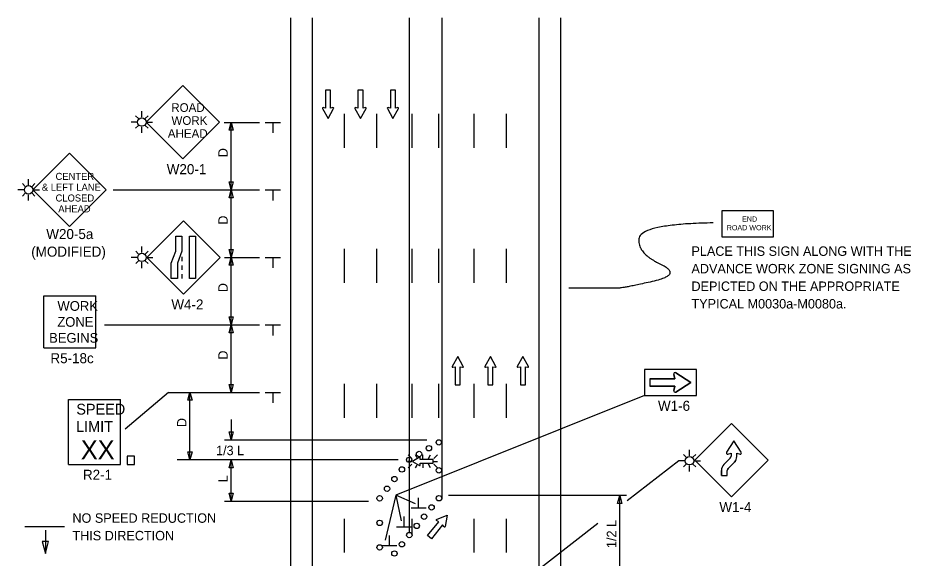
# Model space of a CAD drawing. Extents: x 16038 to 19504, y 5710 to 8321.
# Drawn here: x 16736 to 17399, y 6525 to 6925 of the extents above; entities that cross this region are included whole.
import ezdxf

# ---------------------------------------------------------------- set-up
doc = ezdxf.new("R2010")
doc.units = 0
for name, color, linetype in [('ALI_LEGAL_EX', 7, 'Continuous'), ('Level 3', 7, 'Continuous'), ('MT_SCRATCH_LEVEL_E', 7, 'Continuous'), ('PAVT_EDGE_EX', 7, 'Continuous'), ('TRAFFIC_SIGNS_PR', 7, 'Continuous'), ('TYPICAL_EX', 7, 'Continuous'), ('TYPICAL_TEXT_DIMEN_PR', 7, 'Continuous')]:
    doc.layers.add(name, color=color, linetype=linetype)

msp = doc.modelspace()

# ---------------------------------------------------------------- linework, layer by layer
at = {"layer": 'ALI_LEGAL_EX'}
for points in [[(16978.71, 6829.12), (16978.71, 6854.12)], [(17002.71, 6829.12), (17002.71, 6854.12)], [(17028.71, 6829.12), (17028.71, 6854.12)], [(17048.71, 6829.12), (17048.71, 6854.12)], [(17074.71, 6829.12), (17074.71, 6854.12)], [(17098.71, 6829.12), (17098.71, 6854.12)], [(16978.71, 6729.12), (16978.71, 6754.12)], [(17002.71, 6729.12), (17002.71, 6754.12)], [(17028.71, 6729.12), (17028.71, 6754.12)], [(17048.71, 6729.12), (17048.71, 6754.12)], [(17074.71, 6729.12), (17074.71, 6754.12)], [(17098.71, 6729.12), (17098.71, 6754.12)], [(16978.71, 6629.12), (16978.71, 6654.12)], [(17002.71, 6629.12), (17002.71, 6654.12)], [(17028.71, 6629.12), (17028.71, 6654.12)], [(17048.71, 6629.12), (17048.71, 6654.12)], [(17074.71, 6629.12), (17074.71, 6654.12)], [(17098.71, 6629.12), (17098.71, 6654.12)], [(16978.71, 6529.12), (16978.71, 6554.12)], [(17028.71, 6542.73), (17028.71, 6554.12)], [(17074.71, 6529.12), (17074.71, 6554.12)], [(17098.71, 6529.12), (17098.71, 6554.12)]]:
    msp.add_lwpolyline(points, dxfattribs=at)
at = {"layer": 'Level 3'}
msp.add_line((16848.03, 6647.88), (16815.91, 6620.5), dxfattribs=at)
at = {"layer": 'MT_SCRATCH_LEVEL_E'}
for p, q in [((16968.31, 6871.76), (16964.57, 6871.76)), ((16964.57, 6871.76), (16964.57, 6858.5)), ((16968.31, 6871.76), (16964.57, 6871.76)), ((16964.57, 6871.76), (16964.57, 6858.5)), ((16968.31, 6858.5), (16968.31, 6871.76)), ((16968.31, 6858.5), (16968.31, 6871.76)), ((16992.38, 6871.76), (16988.64, 6871.76)), ((16988.64, 6871.76), (16988.64, 6858.5)), ((16992.38, 6871.76), (16988.64, 6871.76)), ((16988.64, 6871.76), (16988.64, 6858.5)), ((16992.38, 6858.5), (16992.38, 6871.76)), ((16992.38, 6858.5), (16992.38, 6871.76)), ((17016.45, 6871.76), (17012.71, 6871.76)), ((17012.71, 6871.76), (17012.71, 6858.5)), ((17016.45, 6871.76), (17012.71, 6871.76)), ((17012.71, 6871.76), (17012.71, 6858.5)), ((17016.45, 6858.5), (17016.45, 6871.76)), ((17016.45, 6858.5), (17016.45, 6871.76)), ((16962.31, 6858.13), (16966.46, 6850.89)), ((16962.31, 6858.13), (16966.46, 6850.89)), ((16964.57, 6858.5), (16962.79, 6858.82)), ((16964.57, 6858.5), (16962.79, 6858.82)), ((16966.46, 6850.89), (16970.57, 6858.13)), ((16966.46, 6850.89), (16970.57, 6858.13)), ((16970.08, 6858.82), (16968.31, 6858.5)), ((16970.08, 6858.82), (16968.31, 6858.5)), ((16986.38, 6858.13), (16990.53, 6850.89)), ((16986.38, 6858.13), (16990.53, 6850.89)), ((16988.64, 6858.5), (16986.86, 6858.82)), ((16988.64, 6858.5), (16986.86, 6858.82)), ((16990.53, 6850.89), (16994.64, 6858.13)), ((16990.53, 6850.89), (16994.64, 6858.13)), ((16994.16, 6858.82), (16992.38, 6858.5)), ((16994.16, 6858.82), (16992.38, 6858.5)), ((17010.45, 6858.13), (17014.6, 6850.89)), ((17010.45, 6858.13), (17014.6, 6850.89)), ((17012.71, 6858.5), (17010.93, 6858.82)), ((17012.71, 6858.5), (17010.93, 6858.82)), ((17014.6, 6850.89), (17018.71, 6858.13)), ((17014.6, 6850.89), (17018.71, 6858.13)), ((17018.23, 6858.82), (17016.45, 6858.5)), ((17018.23, 6858.82), (17016.45, 6858.5)), ((17062.58, 6674.37), (17058.47, 6667.13)), ((17062.58, 6674.37), (17058.47, 6667.13)), ((17066.73, 6667.13), (17062.58, 6674.37)), ((17066.73, 6667.13), (17062.58, 6674.37)), ((17086.85, 6674.37), (17082.74, 6667.13)), ((17086.85, 6674.37), (17082.74, 6667.13)), ((17090.99, 6667.13), (17086.85, 6674.37)), ((17090.99, 6667.13), (17086.85, 6674.37)), ((17110.92, 6674.37), (17106.81, 6667.13)), ((17110.92, 6674.37), (17106.81, 6667.13)), ((17115.07, 6667.13), (17110.92, 6674.37)), ((17115.07, 6667.13), (17110.92, 6674.37)), ((17058.95, 6666.44), (17060.73, 6666.76)), ((17058.95, 6666.44), (17060.73, 6666.76)), ((17060.73, 6666.76), (17060.73, 6653.5)), ((17060.73, 6666.76), (17060.73, 6653.5)), ((17064.47, 6653.5), (17064.47, 6666.76)), ((17064.47, 6666.76), (17066.25, 6666.44)), ((17064.47, 6653.5), (17064.47, 6666.76)), ((17064.47, 6666.76), (17066.25, 6666.44)), ((17083.22, 6666.44), (17085, 6666.76)), ((17083.22, 6666.44), (17085, 6666.76)), ((17085, 6666.76), (17085, 6653.5)), ((17085, 6666.76), (17085, 6653.5)), ((17088.74, 6653.5), (17088.74, 6666.76)), ((17088.74, 6666.76), (17090.52, 6666.44)), ((17088.74, 6653.5), (17088.74, 6666.76)), ((17088.74, 6666.76), (17090.52, 6666.44)), ((17107.29, 6666.44), (17109.07, 6666.76)), ((17107.29, 6666.44), (17109.07, 6666.76)), ((17109.07, 6666.76), (17109.07, 6653.5)), ((17109.07, 6666.76), (17109.07, 6653.5)), ((17112.81, 6653.5), (17112.81, 6666.76)), ((17112.81, 6666.76), (17114.59, 6666.44)), ((17112.81, 6653.5), (17112.81, 6666.76)), ((17112.81, 6666.76), (17114.59, 6666.44)), ((17060.73, 6653.5), (17064.47, 6653.5)), ((17060.73, 6653.5), (17064.47, 6653.5)), ((17085, 6653.5), (17088.74, 6653.5)), ((17085, 6653.5), (17088.74, 6653.5)), ((17109.07, 6653.5), (17112.81, 6653.5)), ((17109.07, 6653.5), (17112.81, 6653.5)), ((17040.17, 6541.74), (17048.49, 6552.06)), ((17040.17, 6541.74), (17048.49, 6552.06)), ((17048.49, 6552.06), (17046.91, 6552.93)), ((17048.49, 6552.06), (17046.91, 6552.93)), ((17046.96, 6553.77), (17054.73, 6556.81)), ((17046.96, 6553.77), (17054.73, 6556.81)), ((17054.73, 6556.81), (17053.39, 6548.59)), ((17054.73, 6556.81), (17053.39, 6548.59)), ((17051.4, 6549.72), (17043.09, 6539.39)), ((17051.4, 6549.72), (17043.09, 6539.39)), ((17052.59, 6548.36), (17051.4, 6549.72)), ((17052.59, 6548.36), (17051.4, 6549.72)), ((17043.09, 6539.39), (17040.17, 6541.74)), ((17043.09, 6539.39), (17040.17, 6541.74))]:
    msp.add_line(p, q, dxfattribs=at)
for centre, start, end in [((16962.72, 6858.36), 80.03619, 209.77312), ((16962.72, 6858.36), 80.03619, 209.77312), ((16970.16, 6858.36), 330.42484, 99.96381), ((16970.16, 6858.36), 330.42484, 99.96381), ((16986.79, 6858.36), 80.03619, 209.77312), ((16986.79, 6858.36), 80.03619, 209.77312), ((16994.23, 6858.36), 330.42484, 99.96381), ((16994.23, 6858.36), 330.42484, 99.96381), ((17010.86, 6858.36), 80.03619, 209.77312), ((17010.86, 6858.36), 80.03619, 209.77312), ((17018.3, 6858.36), 330.42484, 99.96381), ((17018.3, 6858.36), 330.42484, 99.96381), ((17058.88, 6666.9), 150.42484, 279.96381), ((17058.88, 6666.9), 150.42484, 279.96381), ((17066.32, 6666.9), 260.03619, 29.77312), ((17066.32, 6666.9), 260.03619, 29.77312), ((17083.14, 6666.9), 150.42484, 279.96381), ((17083.14, 6666.9), 150.42484, 279.96381), ((17090.59, 6666.9), 260.03619, 29.77312), ((17090.59, 6666.9), 260.03619, 29.77312), ((17107.22, 6666.9), 150.42484, 279.96381), ((17107.22, 6666.9), 150.42484, 279.96381), ((17114.66, 6666.9), 260.03619, 29.77312), ((17114.66, 6666.9), 260.03619, 29.77312), ((17047.14, 6553.34), 111.38609, 241.12301), ((17047.14, 6553.34), 111.38609, 241.12301), ((17052.94, 6548.67), 221.1954, 350.73437), ((17052.94, 6548.67), 221.1954, 350.73437)]:
    msp.add_arc(centre, 0.463, start, end, dxfattribs=at)
at = {"layer": 'PAVT_EDGE_EX'}
for p, q in [((16954.71, 6925.32), (16954.71, 6077.44)), ((17026.71, 6925.32), (17026.71, 6544.7)), ((17050.71, 6925.32), (17050.71, 6570.98)), ((17122.71, 6925.32), (17122.71, 6077.44)), ((17138.71, 6925.32), (17138.71, 6077.44)), ((17026.71, 6816.67), (17026.71, 6543.65)), ((17050.71, 6816.67), (17050.71, 6568.76)), ((16938.71, 6780.67), (16938.71, 6077.44))]:
    msp.add_line(p, q, dxfattribs=at)
at = {"layer": 'TRAFFIC_SIGNS_PR'}
for p, q in [((16858.67, 6875.33), (16831.49, 6848.14)), ((16885.86, 6848.14), (16858.67, 6875.33)), ((16825.82, 6850.66), (16823.71, 6852.77)), ((16828.33, 6851.7), (16828.33, 6856.2)), ((16830.85, 6850.66), (16832.95, 6852.77)), ((16825.18, 6848.14), (16820.34, 6848.14)), ((16825.82, 6845.63), (16823.71, 6843.52)), ((16828.33, 6840.18), (16828.33, 6844.59)), ((16830.85, 6845.63), (16832.95, 6843.52)), ((16831.49, 6848.14), (16836.37, 6848.14)), ((16831.49, 6848.14), (16858.67, 6820.96)), ((16858.67, 6820.96), (16885.86, 6848.14)), ((16774.75, 6825.07), (16747.57, 6797.88)), ((16801.94, 6797.88), (16774.75, 6825.07)), ((16744.41, 6801.44), (16744.41, 6805.94)), ((16741.26, 6797.88), (16736.42, 6797.88)), ((16741.9, 6800.4), (16739.79, 6802.5)), ((16746.93, 6800.4), (16749.03, 6802.5)), ((16747.57, 6797.88), (16752.45, 6797.88)), ((16747.57, 6797.88), (16774.75, 6770.69)), ((16774.75, 6770.69), (16801.94, 6797.88)), ((16741.9, 6795.37), (16739.79, 6793.26)), ((16744.41, 6789.92), (16744.41, 6794.33)), ((16746.93, 6795.37), (16749.03, 6793.26)), ((16859.31, 6775.01), (16832.16, 6747.86)), ((16886.46, 6747.86), (16859.31, 6775.01)), ((16825.91, 6750.37), (16823.8, 6752.48)), ((16828.42, 6751.41), (16828.42, 6755.91)), ((16830.94, 6750.37), (16833.04, 6752.48)), ((16825.27, 6747.86), (16820.43, 6747.86)), ((16825.91, 6745.35), (16823.8, 6743.24)), ((16828.42, 6739.89), (16828.42, 6744.3)), ((16830.94, 6745.35), (16833.04, 6743.24)), ((16831.58, 6747.86), (16836.46, 6747.86)), ((16832.16, 6747.86), (16859.31, 6720.71)), ((16858.06, 6748.35), (16858.06, 6745.15)), ((16859.31, 6720.71), (16886.46, 6747.86)), ((16858.06, 6741.95), (16858.06, 6738.75)), ((16858.06, 6735.55), (16858.06, 6732.35)), ((16755.78, 6680.91), (16755.78, 6719.31)), ((16755.78, 6719.31), (16794.18, 6719.31)), ((16794.18, 6680.91), (16794.18, 6719.31)), ((16755.78, 6680.91), (16794.18, 6680.91)), ((17205.2, 6658.02), (17223.6, 6658.02)), ((17205.2, 6658.02), (17205.2, 6652.42)), ((17223.6, 6658.02), (17222.76, 6661.08)), ((17224.44, 6662.32), (17235.6, 6655.22)), ((17223.6, 6652.42), (17205.2, 6652.42)), ((17222.76, 6649.36), (17223.6, 6652.42)), ((17235.6, 6655.22), (17224.44, 6648.12)), ((16774.02, 6642.54), (16812.42, 6642.54)), ((16774.02, 6594.54), (16774.02, 6642.54)), ((16812.42, 6594.54), (16812.42, 6642.54)), ((17265.66, 6624.87), (17238.51, 6597.72)), ((17292.81, 6597.72), (17265.66, 6624.87)), ((17234.55, 6600.8), (17234.55, 6605.3)), ((17025.79, 6601.61), (17028.61, 6598.79)), ((17032.51, 6599.43), (17031.25, 6601.61)), ((17036.7, 6598.79), (17036.7, 6601.61)), ((17040.83, 6598.79), (17042.46, 6601.61)), ((17044.78, 6598.79), (17047.6, 6601.61)), ((17232.04, 6599.76), (17229.93, 6601.86)), ((17237.06, 6599.76), (17239.17, 6601.86)), ((17260, 6594.46), (17264.72, 6599.18)), ((17264.72, 6599.18), (17260, 6594.46)), ((16774.02, 6594.54), (16812.42, 6594.54)), ((17028.61, 6596.76), (17025.79, 6596.76)), ((17025.79, 6591.91), (17028.61, 6594.73)), ((17031.23, 6591.91), (17032.44, 6594)), ((17036.7, 6594.73), (17036.7, 6591.91)), ((17042.49, 6591.91), (17040.86, 6594.73)), ((17044.78, 6596.76), (17047.6, 6596.76)), ((17044.78, 6594.73), (17047.6, 6591.91)), ((17231.4, 6597.24), (17226.56, 6597.24)), ((17232.04, 6594.73), (17229.93, 6592.62)), ((17234.55, 6589.28), (17234.55, 6593.69)), ((17237.06, 6594.73), (17239.17, 6592.62)), ((17237.7, 6597.24), (17242.58, 6597.24)), ((17238.51, 6597.72), (17265.66, 6570.56)), ((17263.05, 6591.41), (17267.77, 6596.13)), ((17263.06, 6591.41), (17267.77, 6596.13)), ((17265.66, 6570.56), (17292.81, 6597.72)), ((17258.14, 6586.34), (17258.14, 6590.04)), ((17258.14, 6586.34), (17262.45, 6586.34)), ((17262.45, 6586.34), (17262.45, 6590.04))]:
    msp.add_line(p, q, dxfattribs=at)
for points in [[(17258.49, 6763.22), (17296.89, 6763.22), (17296.89, 6782.42), (17258.49, 6782.42)], [(16858.06, 6763.6), (16858.06, 6752.41), (16854.72, 6743.53), (16854.72, 6732.35), (16850.23, 6732.35), (16850.23, 6743.53), (16853.57, 6752.41), (16853.57, 6763.6)], [(16868.2, 6763.6), (16868.2, 6732.35), (16863.71, 6732.35), (16863.71, 6763.6)], [(17201.2, 6645.62), (17239.6, 6645.62), (17239.6, 6664.82), (17201.2, 6664.82)], [(16817.43, 6594.54), (16823.03, 6594.54), (16823.03, 6600.71), (16817.43, 6600.71)]]:
    msp.add_lwpolyline(points, close=True, dxfattribs=at)
for points in [[(17222.76, 6661.08), (17223.6, 6658.02), (17205.2, 6658.02), (17205.2, 6652.42), (17223.6, 6652.42), (17222.76, 6649.36)], [(17224.44, 6648.12), (17235.6, 6655.22), (17224.44, 6662.32)], [(17272.92, 6603.45), (17267.44, 6612.06), (17261.96, 6603.45)], [(17272.92, 6603.45), (17267.44, 6612.06), (17261.96, 6603.45)], [(17034.37, 6599.78), (17029.06, 6596.76), (17034.37, 6593.72)], [(17034.87, 6594.08), (17034.64, 6595.37), (17044.36, 6595.37), (17044.36, 6598.12), (17034.64, 6598.12), (17034.87, 6599.42)], [(17262.92, 6602.15), (17265.28, 6602.8), (17265.28, 6600.51)], [(17262.92, 6602.15), (17263.75, 6602.38), (17265.28, 6602.8), (17265.28, 6600.51)], [(17269.59, 6600.44), (17269.6, 6602.8), (17271.96, 6602.15)], [(17258.14, 6590.04), (17258.14, 6586.34), (17262.45, 6586.34), (17262.45, 6590.04)]]:
    msp.add_lwpolyline(points, dxfattribs=at)
for centre, radius in [((16828.33, 6848.14), 3.15), ((16744.41, 6797.88), 3.15), ((16828.42, 6747.86), 3.15), ((17048.6, 6610.8), 2), ((17048.6, 6610.8), 2), ((17041.27, 6606.49), 2), ((17026.61, 6597.88), 2), ((17033.94, 6602.19), 2), ((17234.55, 6597.24), 3.15), ((17021.19, 6590.75), 2), ((17048.65, 6590.13), 2), ((17015.7, 6583.62), 2), ((17010.2, 6576.49), 2), ((17048.71, 6569.46), 2), ((17004.71, 6569.36), 2), ((17004.71, 6569.36), 2), ((17004.71, 6569.36), 2), ((17004.71, 6569.36), 2), ((17004.71, 6569.36), 2), ((17043.21, 6562.63), 2), ((17004.71, 6551.18), 2), ((17037.71, 6555.8), 2), ((17032.21, 6548.97), 2), ((17026.71, 6542.14), 2), ((17004.71, 6533), 2), ((17021.21, 6535.31), 2), ((17015.71, 6528.48), 2)]:
    msp.add_circle(centre, radius, dxfattribs=at)
for centre, radius, start, end in [((17223.84, 6661.38), 1.12, 57.53038, 195.32692), ((17223.84, 6661.38), 1.12, 57.53038, 195.32692), ((17223.84, 6649.06), 1.12, 164.67308, 302.46962), ((17223.84, 6649.06), 1.12, 164.67308, 302.46963), ((17034.53, 6599.48), 0.341, 350.73078, 118.89165), ((17262.69, 6602.99), 0.864, 147.52044, 285.3986), ((17262.69, 6602.99), 0.866, 147.52881, 285.38519), ((17263.43, 6600.5), 1.85, 314.2123, 0.1238), ((17263.43, 6600.5), 1.85, 314.21254, 0), ((17263.43, 6600.5), 6.17, 314.21254, 359.38189), ((17263.43, 6600.5), 6.17, 314.76872, 359.37555), ((17272.19, 6602.99), 0.866, 254.67989, 32.28036), ((17034.53, 6594.02), 0.341, 241.48329, 9.95933), ((17264.3, 6590.04), 6.17, 134.21254, 180), ((17264.3, 6590.04), 6.17, 134.21254, 180), ((17264.3, 6590.04), 6.17, 134.21172, 180), ((17264.3, 6590.04), 1.85, 132.37199, 180), ((17264.3, 6590.04), 1.85, 134.21254, 180)]:
    msp.add_arc(centre, radius, start, end, dxfattribs=at)
at = {"layer": 'TYPICAL_EX'}
msp.add_line((16938.71, 6925.32), (16938.71, 6077.44), dxfattribs=at)
at = {"layer": 'TYPICAL_TEXT_DIMEN_PR'}
for p, q in [((16889.35, 6847.88), (16915.61, 6847.88)), ((16889.61, 6847.88), (16915.61, 6847.88)), ((16893.04, 6842.02), (16894.61, 6847.88)), ((16894.61, 6797.88), (16894.61, 6847.88)), ((16894.61, 6847.88), (16896.18, 6842.02)), ((16919.86, 6847.88), (16931.11, 6847.88)), ((16925.49, 6847.88), (16925.49, 6840.1)), ((16894.61, 6842.02), (16893.04, 6842.02)), ((16896.18, 6842.02), (16894.61, 6842.02)), ((16894.61, 6797.88), (16893.04, 6803.74)), ((16893.04, 6803.74), (16894.61, 6803.74)), ((16894.61, 6803.74), (16896.18, 6803.74)), ((16896.18, 6803.74), (16894.61, 6797.88)), ((16807.15, 6797.88), (16915.61, 6797.88)), ((16889.61, 6797.88), (16915.61, 6797.88)), ((16893.04, 6792.02), (16894.61, 6797.88)), ((16894.61, 6797.88), (16896.18, 6792.02)), ((16894.61, 6747.88), (16894.61, 6797.88)), ((16919.86, 6797.88), (16931.11, 6797.88)), ((16925.49, 6797.88), (16925.49, 6790.1)), ((16894.61, 6792.02), (16893.04, 6792.02)), ((16896.18, 6792.02), (16894.61, 6792.02)), ((16894.61, 6747.88), (16893.04, 6753.74)), ((16893.04, 6753.74), (16894.61, 6753.74)), ((16894.61, 6753.74), (16896.18, 6753.74)), ((16896.18, 6753.74), (16894.61, 6747.88)), ((16889.61, 6747.88), (16915.61, 6747.88)), ((16893.04, 6742.02), (16894.61, 6747.88)), ((16894.61, 6747.88), (16896.18, 6742.02)), ((16894.61, 6697.88), (16894.61, 6747.88)), ((16919.86, 6747.88), (16931.11, 6747.88)), ((16925.49, 6747.88), (16925.49, 6740.1)), ((16894.61, 6742.02), (16893.04, 6742.02)), ((16896.18, 6742.02), (16894.61, 6742.02)), ((16800.57, 6697.88), (16915.61, 6697.88)), ((16894.61, 6697.88), (16893.04, 6703.74)), ((16893.04, 6703.74), (16894.61, 6703.74)), ((16893.04, 6692.02), (16894.61, 6697.88)), ((16894.61, 6703.74), (16896.18, 6703.74)), ((16896.18, 6703.74), (16894.61, 6697.88)), ((16894.61, 6647.88), (16894.61, 6697.88)), ((16894.61, 6697.88), (16896.18, 6692.02)), ((16919.86, 6697.88), (16931.11, 6697.88)), ((16925.49, 6697.88), (16925.49, 6690.1)), ((16894.61, 6692.02), (16893.04, 6692.02)), ((16896.18, 6692.02), (16894.61, 6692.02)), ((16894.61, 6647.88), (16893.04, 6653.74)), ((16893.04, 6653.74), (16894.61, 6653.74)), ((16894.61, 6653.74), (16896.18, 6653.74)), ((16896.18, 6653.74), (16894.61, 6647.88)), ((16848.03, 6647.88), (16915.61, 6647.88)), ((16862.46, 6642.02), (16864.03, 6647.88)), ((16864.03, 6647.88), (16865.6, 6642.02)), ((16864.03, 6597.88), (16864.03, 6647.88)), ((16919.86, 6647.88), (16931.11, 6647.88)), ((16925.49, 6647.88), (16925.49, 6640.1)), ((17201.2, 6645.62), (17016.78, 6571.82)), ((16864.03, 6642.02), (16862.46, 6642.02)), ((16865.6, 6642.02), (16864.03, 6642.02)), ((16894.61, 6627.73), (16894.61, 6612.8)), ((16894.61, 6612.8), (16893.04, 6618.67)), ((16893.04, 6618.67), (16894.61, 6618.67)), ((16894.61, 6618.67), (16896.18, 6618.67)), ((16896.18, 6618.67), (16894.61, 6612.8)), ((16889.61, 6612.8), (17039.81, 6612.8)), ((17018.36, 6597.88), (16854.51, 6597.88)), ((16864.03, 6597.88), (16862.46, 6603.74)), ((16862.46, 6603.74), (16864.03, 6603.74)), ((16864.03, 6603.74), (16865.6, 6603.74)), ((16865.6, 6603.74), (16864.03, 6597.88)), ((16893.04, 6592.02), (16894.61, 6597.88)), ((16894.61, 6567.35), (16894.61, 6597.88)), ((16894.61, 6597.88), (16896.18, 6592.02)), ((16894.61, 6592.02), (16893.04, 6592.02)), ((16896.18, 6592.02), (16894.61, 6592.02)), ((17226.56, 6597.24), (17188.25, 6567.51)), ((16894.61, 6567.35), (16893.04, 6573.21)), ((16893.04, 6573.21), (16894.61, 6573.21)), ((16894.61, 6573.21), (16896.18, 6573.21)), ((16896.18, 6573.21), (16894.61, 6567.35)), ((17016.78, 6571.82), (17008.81, 6538.48)), ((17031.18, 6565.37), (17016.78, 6571.82)), ((17016.78, 6571.82), (17020.55, 6552.7)), ((17187.71, 6571.46), (17055.85, 6571.46)), ((17181.14, 6565.6), (17182.71, 6571.46)), ((17182.71, 6514.82), (17182.71, 6571.46)), ((17182.71, 6571.46), (17184.28, 6565.6)), ((16889.61, 6567.35), (16996.54, 6567.35)), ((17033.62, 6562), (17033.62, 6569.78)), ((17182.71, 6565.6), (17181.14, 6565.6)), ((17184.28, 6565.6), (17182.71, 6565.6)), ((17039.24, 6562), (17027.99, 6562)), ((17022.79, 6548.07), (17022.79, 6555.86)), ((16771.04, 6548.22), (16741.6, 6548.22)), ((16756.86, 6545.72), (16756.86, 6528.6)), ((17028.41, 6548.07), (17017.16, 6548.07)), ((17166.55, 6550.67), (17039.04, 6451.72)), ((17011.96, 6534.15), (17011.96, 6541.93)), ((16756.86, 6537.39), (16754.5, 6537.39)), ((16754.5, 6537.39), (16756.86, 6528.6)), ((16756.86, 6528.6), (16759.22, 6537.39)), ((16759.22, 6537.39), (16756.86, 6537.39)), ((17017.58, 6534.15), (17006.33, 6534.15))]:
    msp.add_line(p, q, dxfattribs=at)
msp.add_open_spline([(17252.01, 6773.46), (17198.35, 6772.49), (17195.66, 6751.1), (17229.65, 6735.08), (17185.37, 6725.18), (17180.01, 6725.18), (17144.94, 6725.18)], degree=2, dxfattribs=at)

# ---------------------------------------------------------------- texts
at = {"layer": 'TRAFFIC_SIGNS_PR'}
for s, height, p in [('ROAD', 6.408, (16850.2, 6855.69)), ('WORK', 6.408, (16850.31, 6846.08)), ('AHEAD', 6.408, (16847.62, 6836.46)), ('W20-1', 7.449, (16846.83, 6809.5)), ('CENTER', 5.206, (16764.37, 6805.3)), ('& LEFT LANE', 5.2065, (16754.23, 6797.29)), ('CLOSED', 5.206, (16764.38, 6789.28)), ('AHEAD', 5.206, (16766.4, 6781.27)), ('END', 3.831, (17273.49, 6774.35)), ('ROAD WORK', 3.831, (17262.1, 6767.96)), ('W20-5a', 7.449, (16757.51, 6761.46)), ('(MODIFIED)', 7.449, (16746.35, 6748.41)), ('PLACE THIS SIGN ALONG WITH THE', 7, (17235.95, 6749.02)), ('ADVANCE WORK ZONE SIGNING AS', 7, (17235.95, 6736.02)), ('DEPICTED ON THE APPROPRIATE', 7, (17235.95, 6723.02)), ('TYPICAL M0030a-M0080a.', 7, (17235.95, 6710.02)), ('WORK', 7.217, (16765.78, 6708.28)), ('W4-2', 7.44, (16850.27, 6709.27)), ('ZONE', 7.217, (16765.66, 6696.47)), ('BEGINS', 7.217, (16759.59, 6684.66)), ('R5-18c', 7.44, (16760.59, 6669.47)), ('SPEED', 8, (16779.78, 6631.41)), ('W1-6', 7.44, (17211.14, 6634.18)), ('LIMIT', 8, (16779.62, 6618.61)), ('XX', 14.031, (16783.13, 6598.3)), ('R2-1', 7.44, (16784.69, 6583.1)), ('W1-4', 7.44, (17256.66, 6559.12))]:
    msp.add_text(s, height=height, dxfattribs=at).set_placement(p)
at = {"layer": 'TYPICAL_TEXT_DIMEN_PR'}
for s, p in [('D', (16892.05, 6822.1)), ('D', (16892.05, 6772.1)), ('D', (16892.05, 6722.1)), ('D', (16892.05, 6672.1)), ('D', (16861.47, 6622.1)), ('L', (16892.05, 6581.21)), ('1/2 L', (17180.15, 6532.52))]:
    msp.add_text(s, height=7, rotation=90, dxfattribs=at).set_placement(p)
for s, p in [('1/3 L', (16883.4, 6601.33)), ('NO SPEED REDUCTION', (16776.88, 6551.24)), ('THIS DIRECTION', (16776.88, 6538.24))]:
    msp.add_text(s, height=7, dxfattribs=at).set_placement(p)

doc.saveas('drawing.dxf')
